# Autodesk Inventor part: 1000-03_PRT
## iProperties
Created: 2007-03
Part Number: 1000-03_PRT
Document SubType Name: Modeling
Designer: Andy Moles
Material: Steel
Mass: 0.484152 g
Surface Area: 2.55206 cm^2
Volume: 0.0616754 cm^3
Density: 7.85 g/cm^3
Author: Andy Moles
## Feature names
1. Base1
